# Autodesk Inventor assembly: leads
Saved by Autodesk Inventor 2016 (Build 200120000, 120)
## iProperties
Created: 2018-05
Part Number: leads
Document SubType Name: Assembly
Designer: Administrator
Title: leads
Author: Administrator
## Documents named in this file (3)
- c:\worker\convert-fusion-mar-2018\tmp\job-1\16\output\files\8c58ff39-88bb-4352-afd9-60265520bae5\leads_2.iam
- c:\worker\convert-fusion-mar-2018\tmp\job-1\16\output\files\8c58ff39-88bb-4352-afd9-60265520bae5\top_lead.ipt
- c:\worker\convert-fusion-mar-2018\tmp\job-1\16\output\files\8c58ff39-88bb-4352-afd9-60265520bae5\bottom_lead.ipt
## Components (8 placed, 2 different names)
1. top_lead:1
2. top_lead:5
3. top_lead:6
4. top_lead:7
5. bottom_lead:1
6. bottom_lead:8
7. bottom_lead:9
8. bottom_lead:10
